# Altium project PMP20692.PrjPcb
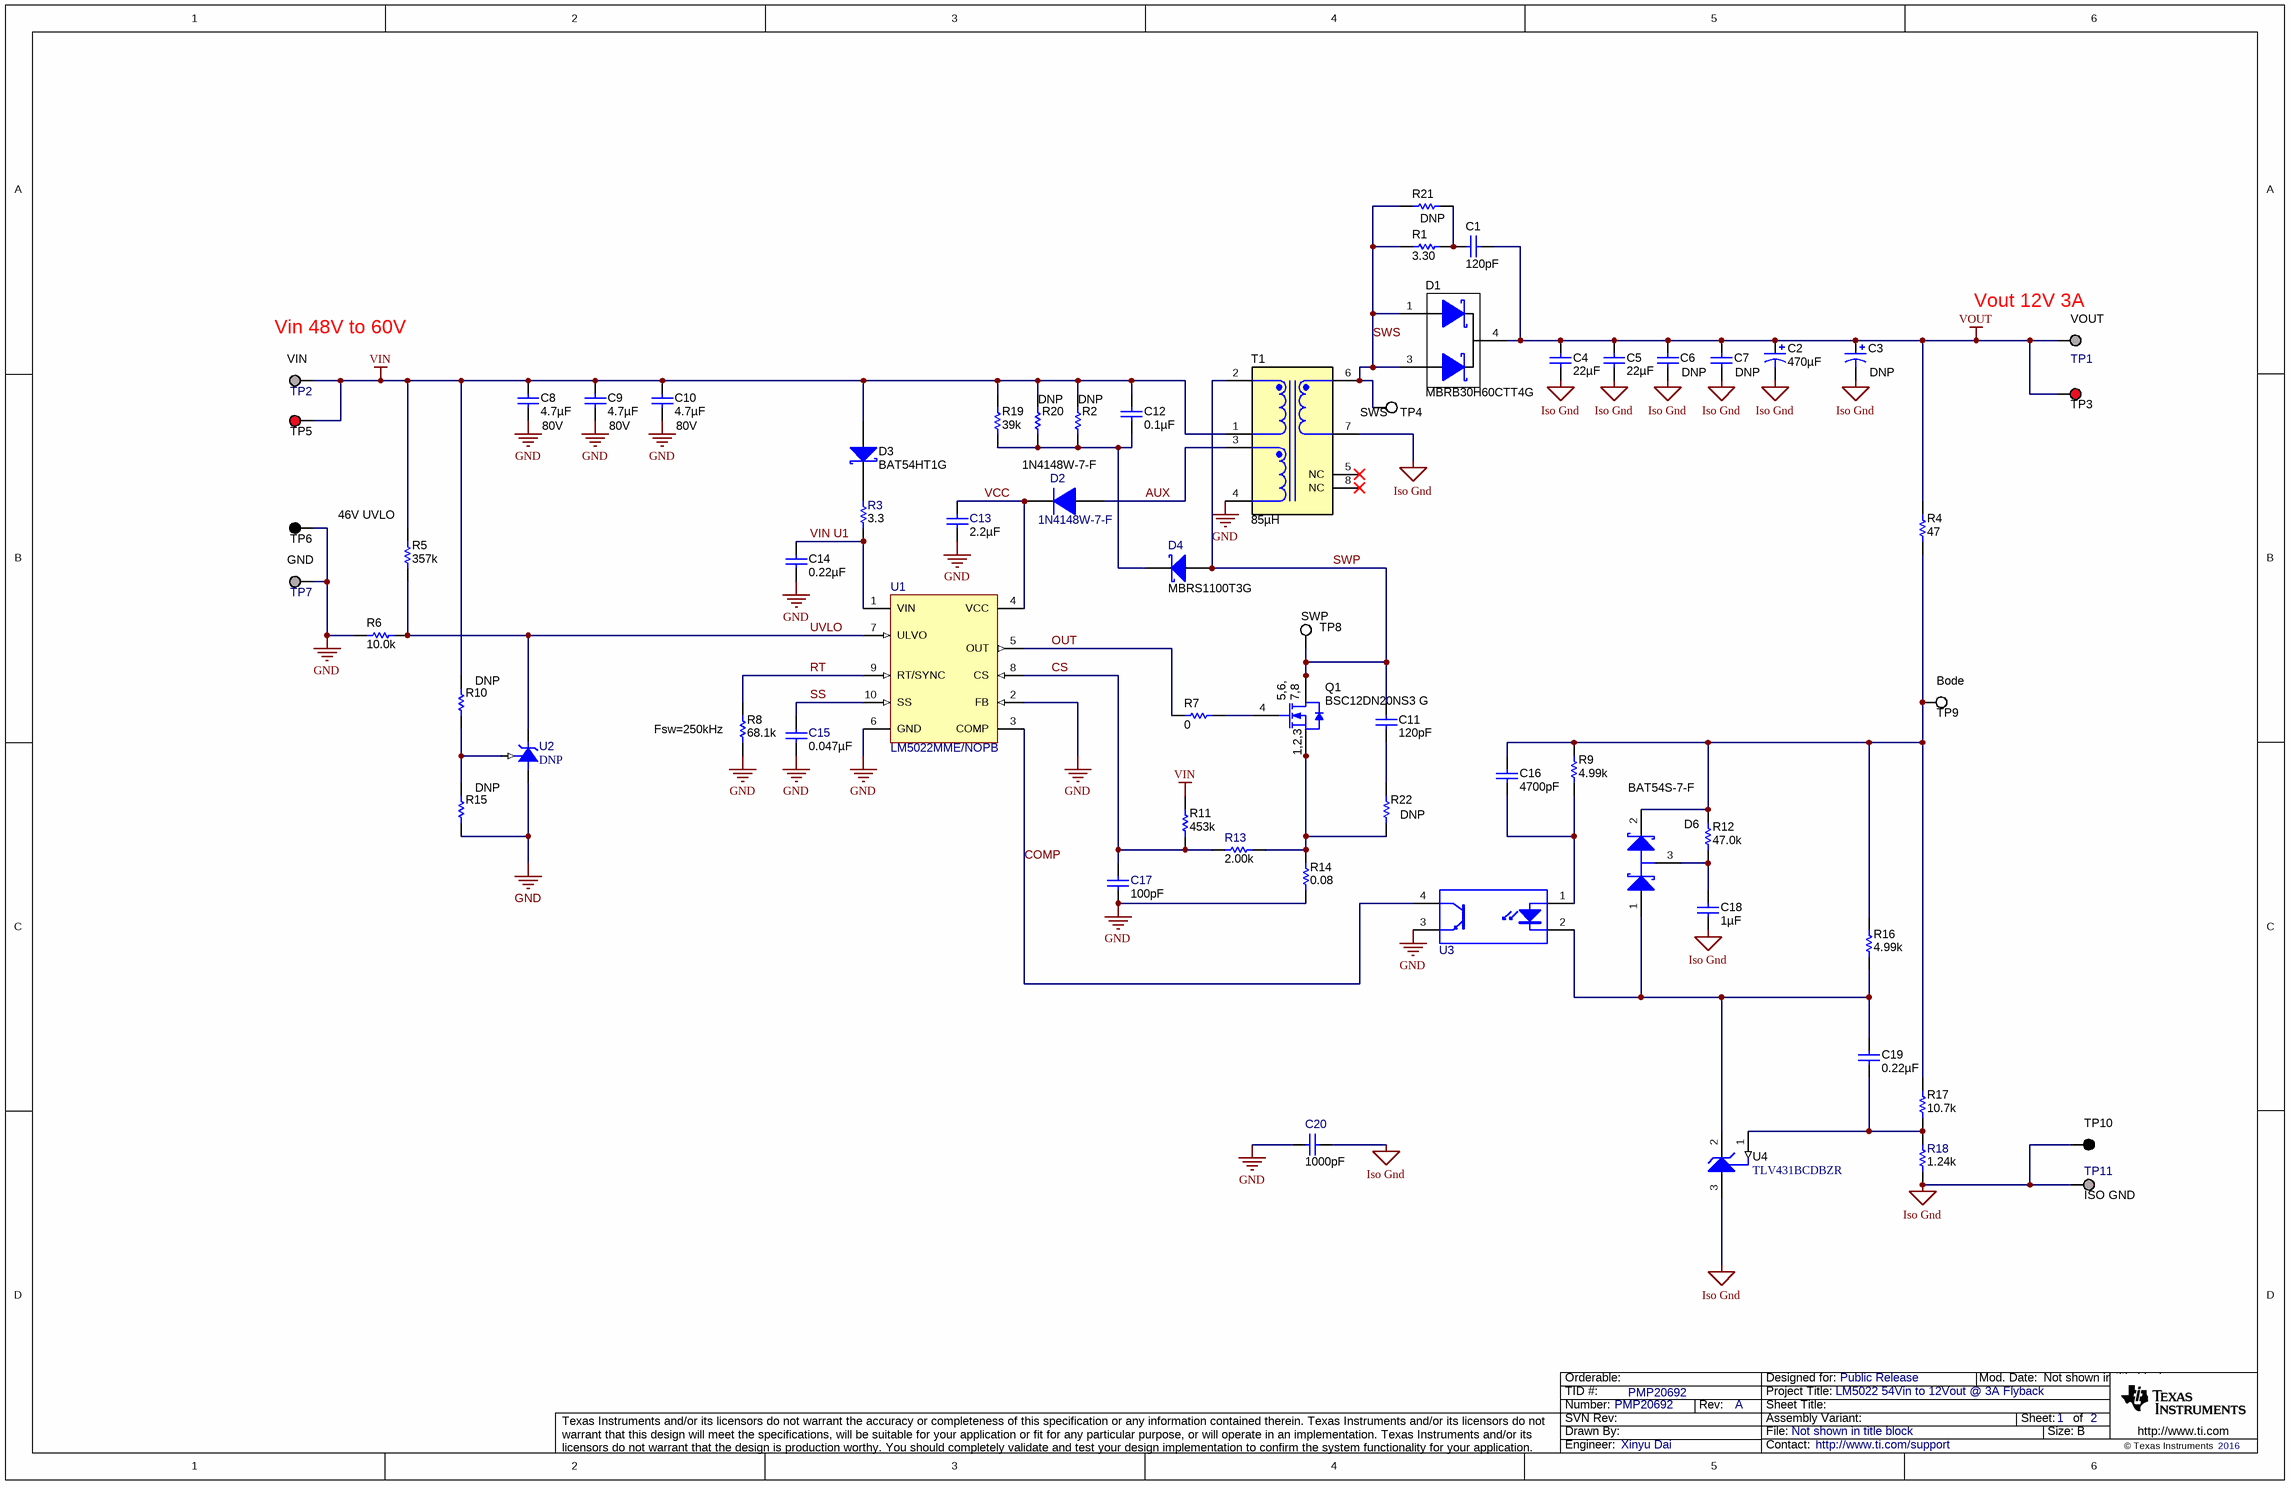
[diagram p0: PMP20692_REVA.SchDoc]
CopyrightYear: 2016; PCB_Layout: Xinyu Dai; PCB_Rev: A; PRJ_Customer: Public Release; PRJ_Engineer: Xinyu Dai; PRJ_Number: PMP20692; PRJ_Title: LM5022 54Vin to 12Vout @ 3A Flyback; SCH_Rev: A; TechSupport: http://www.ti.com/support; TID: PMP20692
2 sheets, 81 parts. Net scope: global (net labels, ports and power ports of the same name join across sheets).
Board file: PMP20551_REVA.PcbDoc
Sheets:
  PMP20692_REVA.SchDoc
  PMP20692_REVA_Hardware.SchDoc

## Sheet PMP20692_REVA.SchDoc
size 431 x 279 mm; Date: Not shown in title block; ApprovedBy: Not shown in title block; CheckedBy: Not shown in title block; Author: Not shown in title block; CompanyName: Not shown in title block; Engineer: Not shown in title block; Organization: Not shown in title block; Address1: Not shown in title block; Address2: Not shown in title block; Address3: Not shown in title block; Address4: Not shown in title block; DocumentNumber: 1; Revision: Use project parameter SCH_Rev; SheetNumber: 1; SheetTotal: 2; PageSetup: Record=PageOptions¦CenterHorizontal=True¦CenterVertical=True¦PrintScale=1.00¦XCorrection=1.00¦YCorrection=1.00¦PrintKind=0¦BorderSize=5000000¦LeftOffset=0¦BottomOffset=0¦Orientation=2¦PaperLength=1000¦PaperWidth=1000¦Scale=100¦PaperSource=15¦PrintQuality=600¦MediaType=1¦DitherType=10¦PaperKind=Letter¦PrintScaleMode=1

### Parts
C1  ValueDisplayed: 120pF  [0805L]  (hidden comment: GRM2165C2A121JA01D)
C2  ValueDisplayed: 470µF  [PSG_800x800]  (hidden comment: APSG160ELL471MH08S)
C3  DNP  [PSG_800x800]
C4  ValueDisplayed: 22µF  [1210L]  (hidden comment: GRM32ER71E226KE15L)
C5  ValueDisplayed: 22µF  [1210L]  (hidden comment: GRM32ER71E226KE15L)
C6  DNP  [1210L]
C7  DNP  [1210L]
C8  ValueDisplayed: 4.7µF  Value2: 80V  [1210L]  (hidden comment: GRM32ER71K475KE14L)
C9  ValueDisplayed: 4.7µF  Value2: 80V  [1210L]  (hidden comment: GRM32ER71K475KE14L)
C10  ValueDisplayed: 4.7µF  Value2: 80V  [1210L]  (hidden comment: GRM32ER71K475KE14L)
C11  ValueDisplayed: 120pF  [0805_HV]  (hidden comment: GRM2165C2A121JA01D)
C12  ValueDisplayed: 0.1µF  [0805L]  (hidden comment: GRM21BR72A104KAC4L)
C13  ValueDisplayed: 2.2µF  [0805L]  (hidden comment: GRM21BR71E225KA73L)
C14  ValueDisplayed: 0.22µF  [0805L]  (hidden comment: GRM21AR72A224KAC5L)
C15  ValueDisplayed: 0.047µF  [0603L]  (hidden comment: GRM188R71C473KA01D)
C16  ValueDisplayed: 4700pF  [0603L]  (hidden comment: GRM188R71H472KA01D)
C17  ValueDisplayed: 100pF  [0603L]  (hidden comment: GRM1885C1H101JA01D)
C18  ValueDisplayed: 1µF  [0603L]  (hidden comment: GRM188R71E105KA12D)
C19  ValueDisplayed: 0.22µF  [0603L]  (hidden comment: GRM188R71E224KA88D)
C20  ValueDisplayed: 1000pF  [1206L]  (hidden comment: GRM31BR73A102KW01L)
D1  MBRB30H60CTT4G  [DDPAK]
D2  1N4148W-7-F  [SOD-123]
D3  BAT54HT1G  [SOD-323]
D4  MBRS1100T3G  [SMB]
D6  BAT54S-7-F  [SOT-23L]
Q1  BSC12DN20NS3 G  [PG-TDSON-8]
R1  ValueDisplayed: 3.30  [1210L]  (hidden comment: CRCW12103R30FKEAHP)
R2  DNP  [1206L]
R3  ValueDisplayed: 3.3  [0805L]  (hidden comment: CRCW08053R30JNEA)
R4  ValueDisplayed: 47  [0603L]  (hidden comment: CRCW060347R0JNEA)
R5  ValueDisplayed: 357k  [0603]  (hidden comment: CRCW0603357KFKEA)
R6  value 10.0k  [0603L]  (hidden comment: CRCW060310K0FKEA)
R7  ValueDisplayed: 0  [0603L]  (hidden comment: CRCW06030000Z0EA)
R8  ValueDisplayed: 68.1k  [0603]  (hidden comment: CRCW060368K1FKEA)
R9  ValueDisplayed: 4.99k  [0603]  (hidden comment: CRCW06034K99FKEA)
R10  DNP  [0603L]
R11  ValueDisplayed: 453k  [0603L]  (hidden comment: CRCW0603453KFKEA)
R12  ValueDisplayed: 47.0k  [0603L]  (hidden comment: CRCW060347K0FKEA)
R13  ValueDisplayed: 2.00k  [0603]  (hidden comment: CRCW06032K00FKEA)
R14  ValueDisplayed: 0.08  [2010]  (hidden comment: WSL2010R0800FEA18)
R15  DNP  [0603L]
R16  ValueDisplayed: 4.99k  [0603]  (hidden comment: CRCW06034K99FKEA)
R17  ValueDisplayed: 10.7k  [0603L]  (hidden comment: CRCW060310K7FKEA)
R18  ValueDisplayed: 1.24k  [0603L]  (hidden comment: CRCW06031K24FKEA)
R19  ValueDisplayed: 39k  [1206L]  (hidden comment: CRCW120639K0JNEA)
R20  DNP  [1206L]
R21  DNP  [1210L]
R22  DNP  [1210L]
T1  ValueDisplayed: 85µH  [UMEC_TG-UT38748S]  (hidden comment: TG-UT38748S)
TP1  VOUT  [Keystone1502-2]
TP2  VIN  [Keystone1502-2]
TP3  5000  [Keystone5000]  (value not drawn)
TP4  SWS  [Keystone5002]
TP5  5000  [Keystone5000]  (value not drawn)
TP6  5001  [Keystone5001]  (value not drawn)
TP7  GND  [Keystone1502-2]
TP8  SWP  [Keystone5002]
TP9  Bode  [Keystone5002]
TP10  5001  [Keystone5001]  (value not drawn)
TP11  ISO GND  [Keystone1502-2]
U1  LM5022MME/NOPB  [MUB10A_N]
U2  DNP  [MF03A_L]
U3  PS2501L-1-F3-L-A  [PS2501L]  (value not drawn)
U4  TLV431BCDBZR  [DBZ0003A_N]

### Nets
GND: C8.2 C9.2 C10.2 C13.2 C14.2 C15.2 C17.2 C20.2 R6.1 R8.1 R14.1 R15.2 T1.4 TP6.1 TP7.1 U1.2(FB) U1.6(GND) U2.3(A) U3.3(E)
Iso Gnd: C2.2(-) C3.2(-) C4.2 C5.2 C6.2 C7.2 C18.2 C20.1 R18.2 T1.7 TP10.1 TP11.1 U4.3(ANODE)
VIN: C8.1 C9.1 C10.1 C12.1 D3.2(A) R2.2 R5.2 R10.1 R11.2 R19.2 R20.2 T1.1 TP2.1 TP5.1
VOUT: C1.1 C2.1(+) C3.1(+) C4.1 C5.1 C6.1 C7.1 D1.4(K) R4.2 TP1.1 TP3.1
AUX: D2.2(A) T1.3
COMP: U1.3(COMP) U3.4(C)
CS: C17.1 R11.1 R13.1 U1.8(CS)
OUT: R7.2 U1.5(OUT)
RT: R8.2 U1.9(RT/SYNC)
SS: C15.1 U1.10(SS)
SWP: C11.1 D4.2(A) Q1.5(D) Q1.6(D) Q1.7(D) Q1.8(D) Q1.9(D) T1.2 TP8.1
SWS: D1.1(A) D1.3(A) R1.1 R21.1 T1.6 TP4.1
UVLO: R5.1 R6.2 U1.7(ULVO) U2.2(K)
VCC: C13.1 D2.1(K) U1.4(VCC)
VIN U1: C14.1 R3.1 U1.1(VIN)
NetC1_2: C1.2 R1.2 R21.2
NetC11_2: C11.2 R22.2
NetC12_2: C12.2 D4.1(K) R2.1 R19.1 R20.1
NetC16_1: C16.1 D6.2(K) R4.1 R9.2 R12.2 R16.1 R17.2 TP9.1
NetC16_2: C16.2 R9.1 U3.1(A)
NetC18_1: C18.1 D6.3(C) R12.1
NetC19_1: C19.1 D6.1(A) R16.2 U3.2(K) U4.2(CATHODE)
NetC19_2: C19.2 R17.1 R18.1 U4.1(REF)
NetD3_1: D3.1(K) R3.2
NetQ1_1: Q1.1(S) Q1.2(S) Q1.3(S) R13.2 R14.2 R22.1
NetQ1_4: Q1.4(G) R7.1
NetR10_2: R10.2 R15.1 U2.1(REF)

Not connected (* = marked no-connect by the designer): T1 5(NC)* 8(NC)*

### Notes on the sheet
- (near TP1) Vout 12V 3A
- (near TP2) Vin 48V to 60V
- (near R5) 46V UVLO
- (near R8) Fsw=250kHz

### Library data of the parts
C1 = GRM2165C2A121JA01D: CAP, CERM, 120 pF, 100 V, +/- 5%, C0G/NP0, 0805; Manufacturer: MuRata; Polarized: N; CompType: Capacitor; Value: 120pF; U/M: EA; Cap_F: 0.00000000012; Tolerance_%: 5; Value1: Unknown; VDC_V: 100; Value2: 100V; TaMin_C: -55; TaMax_C: 125; Cap_Case: 0805; AEC Category: Q200; SizeArea_mm2: 2.5; SizeAreaWB_mm2: 6.75; SizeX_mm: 2; SizeY_mm: 1.25; SizeZ_mm: 1.45
C2 = APSG160ELL471MH08S: CAP, Aluminum Polymer, 470 µF, 16 V, +/- 20%, 0.016 ohm, TH; Manufacturer: Chemi-Con; Polarized: Y; CompType: Capacitor; Value: 470uF; U/M: EA; Cap_F: 0.00047; Tolerance_%: 20; VDC_V: 16; Value2: 16V; ESR_ohm: 0.016; IRMS_A: 4; TaMin_C: -55; TaMax_C: 105; Cap_Case: 8x8mm; AEC Category: Q200; AEC Qualified: N
C3 = APSG160ELL471MH08S: CAP, Aluminum Polymer, 470 µF, 16 V, +/- 20%, 0.016 ohm, TH; Manufacturer: Chemi-Con; Polarized: Y; CompType: Capacitor; Value: 470uF; U/M: EA; ValueDisplayed: 470µF; Cap_F: 0.00047; Tolerance_%: 20; VDC_V: 16; Value2: 16V; ESR_ohm: 0.016; IRMS_A: 4; TaMin_C: -55; TaMax_C: 105; Cap_Case: 8x8mm; AEC Category: Q200; AEC Qualified: N
C4 C5 = GRM32ER71E226KE15L: CAP, CERM, 22 µF, 25 V, +/- 10%, X7R, 1210; Manufacturer: MuRata; Polarized: N; CompType: Capacitor; Value: 22uF; U/M: EA; Cap_F: 0.000022; Tolerance_%: 10; Value1: Unknown; VDC_V: 25; Value2: 25V; TaMin_C: -55; TaMax_C: 125; Cap_Case: 1210; SizeArea_mm2: 8; SizeAreaWB_mm2: 14.7; SizeX_mm: 3.2; SizeY_mm: 2.5; SizeZ_mm: 2.7; AEC Category: Q200
C6 C7 = GRM32ER71E226KE15L: CAP, CERM, 22 µF, 25 V, +/- 10%, X7R, 1210; Manufacturer: MuRata; Polarized: N; CompType: Capacitor; Value: 22uF; ValueDisplayed: 22µF; U/M: EA; Cap_F: 0.000022; Tolerance_%: 10; Value1: Unknown; VDC_V: 25; Value2: 25V; TaMin_C: -55; TaMax_C: 125; Cap_Case: 1210; SizeArea_mm2: 8; SizeAreaWB_mm2: 14.7; SizeX_mm: 3.2; SizeY_mm: 2.5; SizeZ_mm: 2.7; AEC Category: Q200
C8-C10 = GRM32ER71K475KE14L: CAP, CERM, 4.7 µF, 80 V, +/- 10%, X7R, 1210; Manufacturer: MuRata; Polarized: N; CompType: Capacitor; Value: 4.7uF; U/M: EA; Cap_F: 0.0000047; Tolerance_%: 10; Value1: Unknown; VDC_V: 80; TaMin_C: -55; TaMax_C: 125; Cap_Case: 1210; SizeArea_mm2: 8; SizeAreaWB_mm2: 14.7; SizeX_mm: 3.2; SizeY_mm: 2.5; SizeZ_mm: 2.7; AEC Category: Q200
C11 = GRM2165C2A121JA01D: CAP, CERM, 120 pF, 100 V, +/- 5%, C0G/NP0, 0805; Manufacturer: MuRata; Polarized: N; CompType: Capacitor; Value: 120pF; U/M: EA; Cap_F: 0.00000000012; Tolerance_%: 5; Value1: Unknown; VDC_V: 100; Value2: 100V; TaMin_C: -55; TaMax_C: 125; Cap_Case: 0805; SizeArea_mm2: 2.5; SizeAreaWB_mm2: 6.75; SizeX_mm: 2; SizeY_mm: 1.25; SizeZ_mm: 1.45; AEC Category: Q200
C12 = GRM21BR72A104KAC4L: CAP, CERM, 0.1 µF, 100 V, +/- 10%, X7R, 0805; Manufacturer: MuRata; Polarized: N; CompType: Capacitor; Value: 0.1uF; U/M: EA; Cap_F: 0.0000001; Tolerance_%: 10; Value1: Unknown; VDC_V: 100; Value2: 100V; TaMin_C: -55; TaMax_C: 125; Cap_Case: 0805; AEC Category: Q200; SizeArea_mm2: 2.5; SizeAreaWB_mm2: 6.75; SizeX_mm: 2; SizeY_mm: 1.25; SizeZ_mm: 1.45
C13 = GRM21BR71E225KA73L: CAP, CERM, 2.2 µF, 25 V, +/- 10%, X7R, 0805; Manufacturer: MuRata; Cap_Case: 0805; ESR_ohm: 0.005; Polarized: N; TaMax_C: 125; TaMin_C: -55; Tolerance_%: 10; VDC_V: 25; Cap_F: 0.0000022; CompType: Capacitor; Value: 2.2uF; U/M: EA; Value1: 0.005 ohm; Value2: 25V; SizeArea_mm2: 2.5; SizeAreaWB_mm2: 6.75; SizeX_mm: 2; SizeY_mm: 1.25; SizeZ_mm: 1.45; AEC Category: Q200
C14 = GRM21AR72A224KAC5L: CAP, CERM, 0.22 µF, 100 V, +/- 10%, X7R, 0805; Manufacturer: MuRata; Polarized: N; CompType: Capacitor; Value: 0.22uF; U/M: EA; Cap_F: 0.00000022; Tolerance_%: 10; Value1: Unknown; VDC_V: 100; Value2: 100V; TaMin_C: -55; TaMax_C: 125; Cap_Case: 0805; SizeArea_mm2: 2.5; SizeAreaWB_mm2: 6.75; SizeX_mm: 2; SizeY_mm: 1.25; SizeZ_mm: 1.45; AEC Category: Q200
C15 = GRM188R71C473KA01D: CAP, CERM, 0.047 µF, 16 V, +/- 10%, X7R, 0603; Manufacturer: MuRata; Cap_Case: 0603; Polarized: N; TaMax_C: 125; TaMin_C: -55; Tolerance_%: 10; VDC_V: 16; Cap_F: 0.000000047; CompType: Capacitor; Value: 0.047uF; Value1: Unknown; Value2: 16V; U/M: EA; SizeArea_mm2: 1.28; SizeAreaWB_mm2: 4.68; SizeX_mm: 1.6; SizeY_mm: 0.8; SizeZ_mm: 1; AEC Category: Q200
C16 = GRM188R71H472KA01D: CAP, CERM, 4700 pF, 50 V, +/- 10%, X7R, 0603; Manufacturer: MuRata; Polarized: N; CompType: Capacitor; Value: 4700pF; U/M: EA; Cap_F: 0.0000000047; Tolerance_%: 10; Value1: Unknown; VDC_V: 50; Value2: 50V; TaMin_C: -55; TaMax_C: 125; Cap_Case: 0603; AEC Category: Q200; SizeArea_mm2: 1.28; SizeAreaWB_mm2: 4.68; SizeX_mm: 1.6; SizeY_mm: 0.8; SizeZ_mm: 1
C17 = GRM1885C1H101JA01D: CAP, CERM, 100 pF, 50 V, +/- 5%, C0G/NP0, 0603; Manufacturer: MuRata; Cap_Case: 0603; Polarized: N; TaMax_C: 125; TaMin_C: -55; Tolerance_%: 5; VDC_V: 50; Cap_F: 0.0000000001; CompType: Capacitor; Value: 100pF; Value1: Unknown; Value2: 50V; U/M: EA; SizeArea_mm2: 1.28; SizeAreaWB_mm2: 4.68; SizeX_mm: 1.6; SizeY_mm: 0.8; SizeZ_mm: 1; AEC Category: Q200
C18 = GRM188R71E105KA12D: CAP, CERM, 1 µF, 25 V, +/- 10%, X7R, 0603; Manufacturer: MuRata; Polarized: N; CompType: Capacitor; Value: 1uF; U/M: EA; Cap_F: 0.000001; Tolerance_%: 10; Value1: Unknown; VDC_V: 25; Value2: 25V; TaMin_C: -55; TaMax_C: 125; Cap_Case: 0603; AEC Category: Q200; SizeArea_mm2: 1.28; SizeAreaWB_mm2: 4.68; SizeX_mm: 1.6; SizeY_mm: 0.8; SizeZ_mm: 1
C19 = GRM188R71E224KA88D: CAP, CERM, 0.22 µF, 25 V, +/- 10%, X7R, 0603; Manufacturer: MuRata; Polarized: N; CompType: Capacitor; Value: 0.22uF; U/M: EA; Cap_F: 0.00000022; Tolerance_%: 10; Value1: Unknown; VDC_V: 25; Value2: 25V; TaMin_C: -55; TaMax_C: 125; Cap_Case: 0603; AEC Category: Q200; SizeArea_mm2: 1.28; SizeAreaWB_mm2: 4.68; SizeX_mm: 1.6; SizeY_mm: 0.8; SizeZ_mm: 1
C20 = GRM31BR73A102KW01L: CAP, CERM, 1000 pF, 1000 V, +/- 10%, X7R, 1206; Manufacturer: MuRata; Cap_Case: 1206; Polarized: N; TaMax_C: 125; TaMin_C: -55; Tolerance_%: 10; VDC_V: 1000; Cap_F: 0.000000001; CompType: Capacitor; Value: 1000pF; Value1: Unknown; Value2: 1000V; U/M: EA; SizeArea_mm2: 5.12; SizeAreaWB_mm2: 10.92; SizeX_mm: 3.2; SizeY_mm: 1.6; SizeZ_mm: 1.35; AEC Category: Q200
D1 = MBRB30H60CTT4G: Diode, Schottky, 60 V, 15 A, AEC-Q101, DDPAK; Manufacturer: ON Semiconductor; U/M: EA; Value1: 15A; Value: 60V; Vf_V: 0.62; Value2: 0.62V; Io_A: 15; Vr_V: 60; TJmax_C: 175; RJC_CperW: 1.6; AEC Category: Q101; AEC Qualified: Y; SizeAreaWB_mm2: 209.6992; SizeArea_mm2: 154.8892; SizeX_mm: 15.245; SizeY_mm: 10.16; SizeZ_mm: 4.445
D2 = 1N4148W-7-F: Diode, Ultrafast, 100V, 0.15A, SOD-123; Manufacturer: Diodes Inc.; U/M: EA; Vf_V: 1.25; Io_A: 0.15; Vr_V: 100; TJmax_C: 150; Value: 1.25V
D3 = BAT54HT1G: Diode, Schottky, 30 V, 0.2 A, SOD-323; Manufacturer: ON Semiconductor; Value: 30V; U/M: EA; Vf_V: 0.35; Io_A: 0.2; Value1: 0.2A; Vr_V: 30; Value2: 0.35V; SizeAreaWB_mm2: 8.695; SizeArea_mm2: 3.645; SizeX_mm: 2.7; SizeY_mm: 1.35; SizeZ_mm: 1; AEC Category: Q101
D4 = MBRS1100T3G: Diode, Schottky, 100 V, 1 A, SMB; Manufacturer: ON Semiconductor; RJC_CperW: 22; Vf_V: 0.75; Io_A: 1; Vr_V: 100; TJmax_C: 150; Value: 100V; U/M: EA; Value1: 1A; Value2: 0.75V; SizeAreaWB_mm2: 44.156; SizeArea_mm2: 21.336; SizeX_mm: 5.6; SizeY_mm: 3.81; SizeZ_mm: 2.6; AEC Category: Q101
D6 = BAT54S-7-F: Diode, Schottky, 30 V, 0.2 A, SOT-23; Manufacturer: Diodes Inc.; U/M: EA; Vf_V: 0.65; Value: 30V; Value1: 0.2A; Value2: 0.65V; Io_A: 0.2; Vr_V: 30; TJmax_C: 125; SizeAreaWB_mm2: 14; SizeArea_mm2: 7.5; SizeX_mm: 2.5; SizeY_mm: 3; SizeZ_mm: 1.1; AEC Category: Q101
Q1 = BSC12DN20NS3 G: MOSFET, N-CH, 200 V, 11.3 A, PG-TDSON-8; Manufacturer: Infineon Technologies; Alternate Manufacturer: None; Value: 200V; U/M: EA; ChType: N; VdsMax_V: 200; Value1: ? ohm; Value2: 6.5 nC; QgTyp_nC: 6.5; Vgs_V: 20; IdsMax_A: 11.3; AEC Category: Q101; SizeAreaWB_mm2: 55.131; SizeArea_mm2: 29.351; SizeX_mm: 5.99; SizeY_mm: 4.9; SizeZ_mm: 1.12
R1 R21 R22 = CRCW12103R30FKEAHP: RES, 3.30, 1%, 0.75 W, AEC-Q200 Grade 0, 1210; Manufacturer: Vishay-Dale; CompType: Resistor; Value: 3.30; Res_ohm: 3.3; Value_Code: 3R30; Tolerance_%: 1; Power_W: 0.75; Value2: 0.75W; TempCo: 100 ppm/C; SizeArea_mm2: 8; SizeAreaWB_mm2: 14.7; SizeX_mm: 3.2; SizeY_mm: 2.5; SizeZ_mm: 1.35; U/M: EA; AEC Category: Q200; AEC Qualified: Y; AEC Grade: 0
R2 = CRCW120639K0JNEA: RES, 39 k, 5%, 0.25 W, 1206; Manufacturer: Vishay-Dale; CompType: Resistor; Value: 39k; Res_ohm: 39000; Value_Code: 39k0; Tolerance_%: 5; Power_W: 0.25; Value2: 0.25W; VDC_V: 200; TempCo: 200 ppm/C; EIA_Code: E24; U/M: EA; SizeArea_mm2: 5.12; SizeX_mm: 3.2; SizeY_mm: 1.6; SizeZ_mm: 1.35; AEC Category: Q200
R3 = CRCW08053R30JNEA: RES, 3.3, 5%, 0.125 W, 0805; Manufacturer: Vishay-Dale; CompType: Resistor; Tolerance_%: 5; VDC_V: 150; Power_W: 0.125; Value: 3.3; Value_Code: 3R30; Value2: 0.125W; EIA_Code: E24; U/M: EA; TempCo: 200 ppm/C; SizeArea_mm2: 2.5; SizeX_mm: 2; SizeY_mm: 1.25; SizeZ_mm: 1.45; AEC Category: Q200
R4 = CRCW060347R0JNEA: RES, 47, 5%, 0.1 W, 0603; Manufacturer: Vishay-Dale; CompType: Resistor; Value: 47; Value_Code: 47R0; Tolerance_%: 5; Power_W: 0.1; Value2: 0.1W; VDC_V: 75; TempCo: 200 ppm/C; EIA_Code: E24; U/M: EA; SizeArea_mm2: 1.28; SizeX_mm: 1.6; SizeY_mm: 0.8; SizeZ_mm: 1; AEC Category: Q200
R5 = CRCW0603357KFKEA: RES, 357 k, 1%, 0.1 W, 0603; Manufacturer: Vishay-Dale; CompType: Resistor; Value: 357k; Res_ohm: 357000; Tolerance_%: 1; Power_W: 0.1; Value2: 0.1W; VDC_V: 75; TempCo: 100 ppm/C; EIA_Code: E96; U/M: EA; SizeArea_mm2: 1.28; SizeX_mm: 1.6; SizeY_mm: 0.8; AEC Category: Q200
R6 = CRCW060310K0FKEA: RES, 10.0k ohm, 1%, 0.1W, 0603; Manufacturer: Vishay-Dale; CompType: Resistor; Res_ohm: 10000; Value_Code: 10k0; Tolerance_%: 1; Power_W: 0.1; VDC_V: 75; TempCo: 100 ppm/C; EIA_Code: E96; U/M: EA
R7 = CRCW06030000Z0EA: RES, 0, 5%, 0.1 W, 0603; Manufacturer: Vishay-Dale; CompType: Resistor; Value: 0; Value_Code: 0000; Tolerance_%: 5; Power_W: 0.1; Value2: 0.1W; VDC_V: 75; TempCo: 200 ppm/C; EIA_Code: E24; U/M: EA; AEC Category: Q200; SizeArea_mm2: 1.28; SizeX_mm: 1.6; SizeY_mm: 0.8; SizeZ_mm: 1
R8 = CRCW060368K1FKEA: RES, 68.1 k, 1%, 0.1 W, 0603; Manufacturer: Vishay-Dale; CompType: Resistor; Value: 68.1k; Res_ohm: 68100; Value_Code: 68k1; Tolerance_%: 1; Power_W: 0.1; Value2: 0.1W; VDC_V: 75; TempCo: 100 ppm/C; EIA_Code: E96; U/M: EA; AEC Category: Q200; SizeArea_mm2: 1.28; SizeX_mm: 1.6; SizeY_mm: 0.8
R9 = CRCW06034k99FKEA: RES, 4.99 k, 1%, 0.1 W, 0603; Manufacturer: Vishay-Dale; CompType: Resistor; Value: 4.99k; Res_ohm: 4990; Value_Code: 4k99; Tolerance_%: 1; Power_W: 0.1; Value2: 0.1W; VDC_V: 75; TempCo: 100 ppm/C; EIA_Code: E96; U/M: EA; SizeArea_mm2: 1.28; SizeX_mm: 1.6; SizeY_mm: 0.8; AEC Category: Q200
R10 = CRCW0603523KFKEA: RES, 523 k, 1%, 0.1 W, 0603; Manufacturer: Vishay-Dale; CompType: Resistor; Value: 523k; Res_ohm: 523000; Tolerance_%: 1; Power_W: 0.1; Value2: 0.1W; VDC_V: 75; TempCo: 100 ppm/C; EIA_Code: E96; U/M: EA; SizeArea_mm2: 1.28; SizeX_mm: 1.6; SizeY_mm: 0.8; AEC Category: Q200
R11 = CRCW0603453KFKEA: RES, 453 k, 1%, 0.1 W, 0603; Manufacturer: Vishay-Dale; CompType: Resistor; Value: 453k; Res_ohm: 453000; Tolerance_%: 1; Power_W: 0.1; Value2: 0.1W; VDC_V: 75; TempCo: 100 ppm/C; SizeArea_mm2: 1.28; SizeX_mm: 1.6; SizeY_mm: 0.8; EIA_Code: E96; U/M: EA; AEC Category: Q200
R12 = CRCW060347K0FKEA: RES, 47.0 k, 1%, 0.1 W, AEC-Q200 Grade 0, 0603; Manufacturer: Vishay-Dale; CompType: Resistor; Value: 47.0k; Res_ohm: 47000; Value_Code: 47k0; Tolerance_%: 1; Power_W: 0.1; Value2: 0.1W; VDC_V: 75; TempCo: 100 ppm/C; U/M: EA; SizeArea_mm2: 1.28; SizeX_mm: 1.6; SizeY_mm: 0.8; AEC Category: Q200; AEC Qualified: Y; AEC Grade: 0
R13 = CRCW06032K00FKEA: RES, 2.00 k, 1%, 0.1 W, 0603; Manufacturer: Vishay-Dale; CompType: Resistor; Tolerance_%: 1; VDC_V: 75; Power_W: 0.1; Res_ohm: 2000; Value: 2.00k; Value_Code: 2k00; Value2: 0.1W; TempCo: 100 ppm/C; EIA_Code: E96; U/M: EA; AEC Category: Q200; SizeArea_mm2: 1.28; SizeX_mm: 1.6; SizeY_mm: 0.8
R14 = WSL2010R0800FEA18: RES, 0.08, 1%, 1 W, AEC-Q200 Grade 0, 2010; Manufacturer: Vishay-Dale; CompType: Resistor; Value: 0.08; Value_Code: R080; Tolerance_%: 1; Value2: 1W; TempCo: 75 ppm/C; SizeArea_mm2: 12.5; SizeX_mm: 5; SizeY_mm: 2.5; SizeZ_mm: 1.66; U/M: EA; AEC Category: Q200; AEC Qualified: Y; AEC Grade: 0
R15 = CRCW060310K2FKEA: RES, 10.2 k, 1%, 0.1 W, 0603; Manufacturer: Vishay-Dale; CompType: Resistor; Value: 10.2k; Res_ohm: 10200; Value_Code: 10k2; Tolerance_%: 1; Power_W: 0.1; Value2: 0.1W; VDC_V: 75; TempCo: 100 ppm/C; EIA_Code: E96; U/M: EA; SizeArea_mm2: 1.28; SizeX_mm: 1.6; SizeY_mm: 0.8; AEC Category: Q200
R16 = CRCW06034k99FKEA: RES, 4.99 k, 1%, 0.1 W, 0603; Manufacturer: Vishay-Dale; CompType: Resistor; Value: 4.99k; Res_ohm: 4990; Value_Code: 4k99; Tolerance_%: 1; Power_W: 0.1; Value2: 0.1W; VDC_V: 75; TempCo: 100 ppm/C; EIA_Code: E96; U/M: EA; AEC Category: Q200; SizeArea_mm2: 1.28; SizeX_mm: 1.6; SizeY_mm: 0.8
R17 = CRCW060310K7FKEA: RES, 10.7 k, 1%, 0.1 W, 0603; Manufacturer: Vishay-Dale; CompType: Resistor; Value: 10.7k; Res_ohm: 10700; Value_Code: 10k7; Tolerance_%: 1; Power_W: 0.1; Value2: 0.1W; VDC_V: 75; TempCo: 100 ppm/C; EIA_Code: E96; U/M: EA; AEC Category: Q200; SizeArea_mm2: 1.28; SizeX_mm: 1.6; SizeY_mm: 0.8
R18 = CRCW06031K24FKEA: RES, 1.24 k, 1%, 0.1 W, 0603; Manufacturer: Vishay-Dale; CompType: Resistor; Tolerance_%: 1; VDC_V: 75; Power_W: 0.1; Res_ohm: 1240; Value: 1.24k; Value_Code: 1k24; Value2: 0.1W; TempCo: 100 ppm/C; EIA_Code: E96; U/M: EA; AEC Category: Q200; SizeArea_mm2: 1.28; SizeX_mm: 1.6; SizeY_mm: 0.8
R19 R20 = CRCW120639K0JNEA: RES, 39 k, 5%, 0.25 W, 1206; Manufacturer: Vishay-Dale; CompType: Resistor; Value: 39k; Res_ohm: 39000; Value_Code: 39k0; Tolerance_%: 5; Power_W: 0.25; Value2: 0.25W; VDC_V: 200; TempCo: 200 ppm/C; SizeArea_mm2: 5.12; SizeX_mm: 3.2; SizeY_mm: 1.6; SizeZ_mm: 1.35; EIA_Code: E24; U/M: EA; AEC Category: Q200
T1 = TG-UT38748S: Transformer, 85 uH, SMT; Manufacturer: Universal Microelectronics; SymbolCreator: Altium; Value: 85uH; Lp: 85; DCR_ohm: 0.1056; LeakageL: 1.2; Ns1toNp: 0.25; Rs1: 0.009; SizeAreaWB_mm2: 540; SizeArea_mm2: 451; SizeX_mm: 22; SizeY_mm: 20.5; SizeZ_mm: 13.3
TP1 TP2 TP7 TP11 = 1502-2: Terminal, Turret, TH, Double; Manufacturer: Keystone; Alternate Manufacturer: Any; Alternate PartNumber: Equivalent; CompType: Turret Terminal; U/M: EA
TP3 TP5 = 5000: Test Point, TH, Miniature, Red; Manufacturer: Keystone; Alternate Manufacturer: Any; Alternate PartNumber: Equivalent; CompType: Test Point Loop; U/M: EA
TP4 TP8 TP9 = 5002: Test Point, TH, Miniature, White; Manufacturer: Keystone; Alternate Manufacturer: Any; Alternate PartNumber: Equivalent; CompType: Test Point Loop; U/M: EA
TP6 TP10 = 5001: Test Point, TH, Miniature, Black; Manufacturer: Keystone; Alternate Manufacturer: Any; Alternate PartNumber: Equivalent; CompType: Test Point Loop; U/M: EA
U1 = LM5022MME/NOPB: 60V Low Side Controller for Boost and SEPIC, 10-pin MSOP, Pb-Free; Manufacturer: Texas Instruments; CompType: Switcher; PackageTopMarking: ZXTT*5022; PowerWise: Y
U2 = LMV431BIMFX/NOPB: Low-Voltage (1.24V) Adjustable Precision Shunt Regulators, 3-pin SOT-23, Pb-Free; Manufacturer: Texas Instruments; PackageTopMarking: RLB*XTT; PowerWise: N; CompType: MiscPower
U3 = PS2501L-1-F3-L-A: Optocoupler, 5 kV, 200-400% CTR, SMT; Manufacturer: California Eastern Laboratories; SymbolCreator: a0412235; CTR (Min): 200%; CTR (Max): 400%; Voltage_Isolation_Vrms: 5000V
U4 = TLV431BCDBZR: Low-Voltage Adjustable Precision Shunt Regulator, 15 mA, 0 to 70 degC, 3-pin SOT-23 (DBZ), Green (RoHS & no Sb/Br); Manufacturer: Texas Instruments; Alternate PartNumber: Equivalent; Initial Accuracy @ 25/deg C(%): 0.5; Iout/Iz(Max)(mA): 15; Min Iz for Regulation(uA): 80; Rating: Catalog; SubFamily: Shunt Voltage Reference; Temp Coeff(Max)(ppm/ degree C): 129; VO Adj(Max)(V): 6; VO Adj(Min)(V): 1.24

## Sheet PMP20692_REVA_Hardware.SchDoc
size 431 x 279 mm; Date: Not shown in title block; ApprovedBy: Not shown in title block; CheckedBy: Not shown in title block; Author: Not shown in title block; CompanyName: Not shown in title block; Engineer: Not shown in title block; Organization: Not shown in title block; Address1: Not shown in title block; Address2: Not shown in title block; Address3: Not shown in title block; Address4: Not shown in title block; DocumentNumber: 2; Revision: Use project parameter SCH_Rev; SheetNumber: 2; SheetTotal: 2; PageSetup: Record=PageOptions¦CenterHorizontal=True¦CenterVertical=True¦PrintScale=1.00¦XCorrection=1.00¦YCorrection=1.00¦PrintKind=0¦BorderSize=5000000¦LeftOffset=0¦BottomOffset=0¦Orientation=2¦PaperLength=1000¦PaperWidth=1000¦Scale=100¦PaperSource=15¦PrintQuality=600¦MediaType=1¦DitherType=10¦PaperKind=Letter¦PrintScaleMode=1
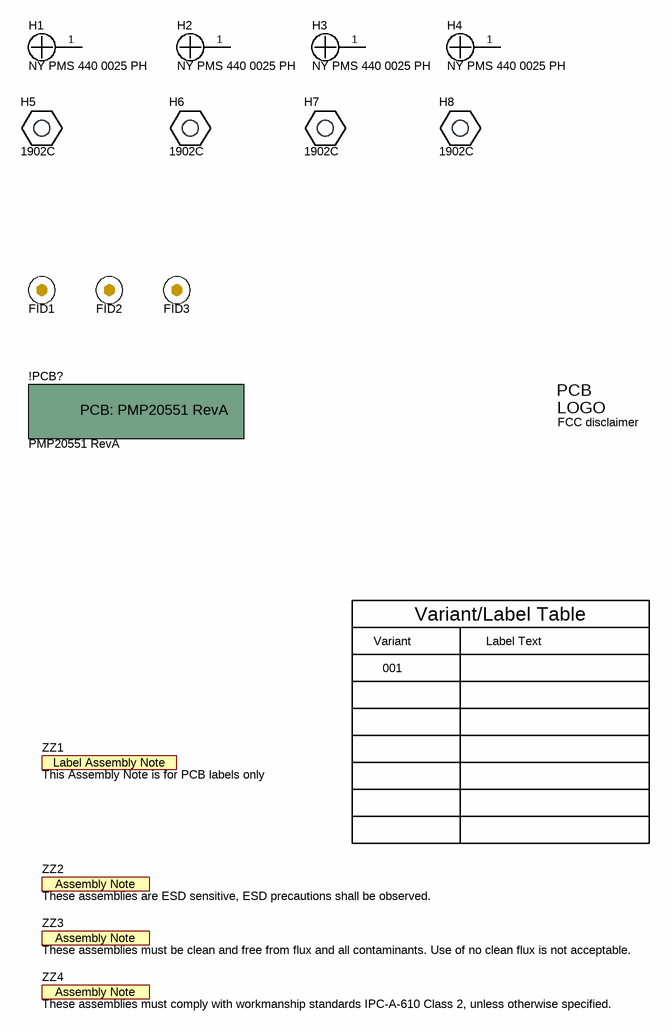
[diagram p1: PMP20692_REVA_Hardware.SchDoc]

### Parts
!PCB?  PMP20551 RevA  (mechanical)
FID1  Fiducial  [Fiducial10-20]  (value not drawn)
FID2  Fiducial  [Fiducial10-20]  (value not drawn)
FID3  Fiducial  [Fiducial10-20]  (value not drawn)
H1  NY PMS 440 0025 PH  [NY PMS 440 0025 PH]
H2  NY PMS 440 0025 PH  [NY PMS 440 0025 PH]
H3  NY PMS 440 0025 PH  [NY PMS 440 0025 PH]
H4  NY PMS 440 0025 PH  [NY PMS 440 0025 PH]
H5  1902C  [Keystone_1902C]
H6  1902C  [Keystone_1902C]
H7  1902C  [Keystone_1902C]
H8  1902C  [Keystone_1902C]
Logo3  FCC disclaimer  [FCC_disclaimer]  (no BOM)
ZZ1  This Assembly Note is for PCB labels only  [AssemblyNoteLabel]  (no BOM)
ZZ2  These assemblies are ESD sensitive, ESD precautions shall be observed.  [AssemblyNote]  (no BOM)
ZZ3  These assemblies must be clean and free from flux and all contaminants. Use of no clean flux is not acceptable.  [AssemblyNote]  (no BOM)
ZZ4  These assemblies must comply with workmanship standards IPC-A-610 Class 2, unless otherwise specified.  [AssemblyNote]  (no BOM)

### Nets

Not connected (* = marked no-connect by the designer): H1 1; H2 1; H3 1; H4 1

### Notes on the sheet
- Variant
- Variant/Label Table
- Label Text
- 001

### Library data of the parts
!PCB? = PCB_OtherProject: Manufacturer: Any; SymbolCreator: a0412235; CompType: PCB; U/M: EA
FID1-FID3 = Fiducial: Fiducial mark.  There is nothing to buy or mount.; SymbolCreator: codlsc
H1-H4 = NY PMS 440 0025 PH: Machine Screw, Round, #4-40 x 1/4, Nylon, Philips panhead; Manufacturer: B&F Fastener Supply; CompType: Hardware; SymbolCreator: codlsc; U/M: EA
H5-H8 = 1902C: Standoff, Hex, 0.5"L #4-40 Nylon; Manufacturer: Keystone; CompType: Hardware
Logo3 = FCC_disclaimer: SymbolCreator: codlsc
ZZ1 = AssemblyNoteLabel: SymbolCreator: a0412235
ZZ2-ZZ4 = AssemblyNote: SymbolCreator: codlsc

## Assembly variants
001: not fitted C3 C6 C7 C11 FID1 FID2 FID3 R2 R10 R15 R20 R21 R22 U2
